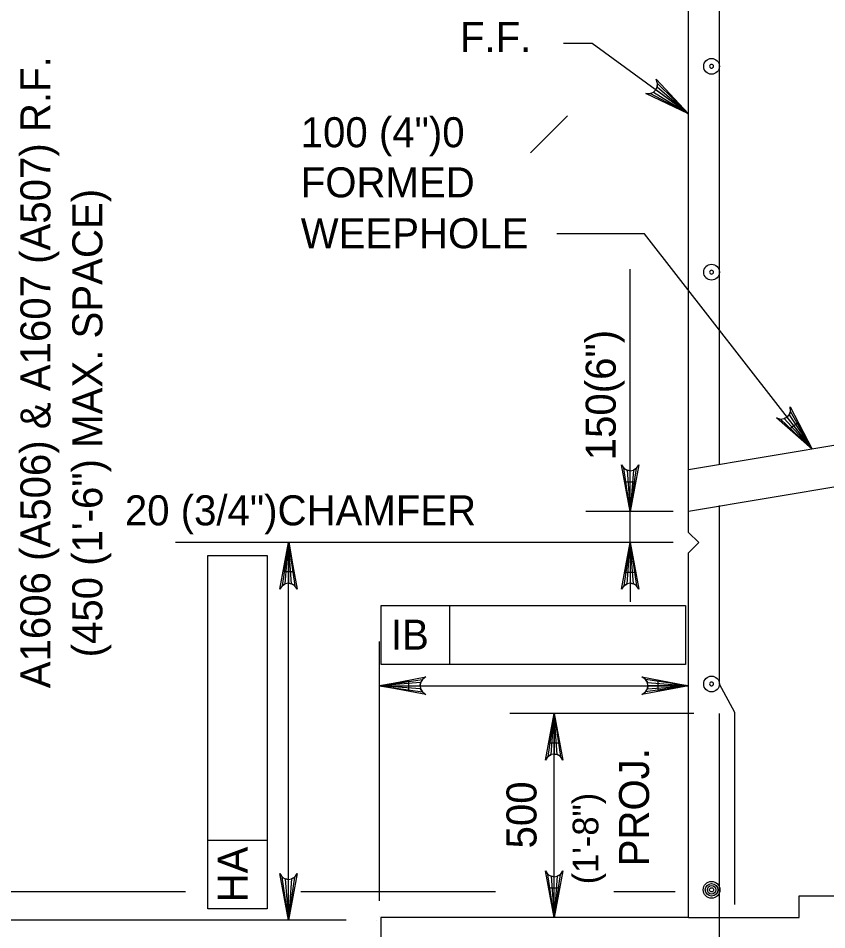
# Model space of a CAD drawing. Extents: x 634540 to 640306, y 296059 to 300275.
# Drawn here: x 639037.4 to 639118.2, y 298220.1 to 298311.1 of the extents above; entities that cross this region are included whole.
import ezdxf

# ---------------------------------------------------------------- set-up
doc = ezdxf.new("R2010")
doc.units = 0
for name, color, linetype in [('3', 7, 'Continuous'), ('4', 7, 'Continuous'), ('5', 7, 'Continuous'), ('6', 7, 'Continuous'), ('7', 7, 'Continuous'), ('9', 7, 'Continuous')]:
    doc.layers.add(name, color=color, linetype=linetype)

# ---------------------------------------------------------------- blocks, each defined once
blk = doc.blocks.new('B')
at = {"layer": '3'}
blk.add_circle((0, 0), 0.16, dxfattribs=at)
for start, end in [(0, 180), (180, 0)]:
    blk.add_arc((0, 0), 0.0391, start, end, dxfattribs=at)

msp = doc.modelspace()

# ---------------------------------------------------------------- linework, layer by layer
at = {"layer": '3'}
for p, q in [((639094.771, 298308.588), (639091.913, 298308.588)), ((639104.407, 298301.563), (639094.771, 298308.588)), ((639088.624, 298297.668), (639092.312, 298301.356)), ((639098.569, 298261.863), (639098.569, 298286.062)), ((639098.569, 298264.815), (639098.569, 298267.769)), ((639102.869, 298261.863), (639094.14, 298261.863)), ((639098.569, 298258.742), (639098.569, 298261.863)), ((639104.407, 298259.769), (639105.432, 298258.742)), ((639102.869, 298258.742), (639053.144, 298258.742)), ((639064.432, 298221.038), (639064.432, 298258.742)), ((639097.848, 298258.742), (639094.14, 298258.742)), ((639098.569, 298258.742), (639098.569, 298252.838)), ((639104.407, 298257.717), (639105.432, 298258.742)), ((639056.388, 298222.165), (639056.388, 298257.467)), ((639056.388, 298257.467), (639062.295, 298257.467)), ((639062.295, 298257.467), (639062.295, 298222.165)), ((639073.706, 298252.469), (639104.084, 298252.469)), ((639073.706, 298246.564), (639073.706, 298252.469)), ((639080.552, 298246.564), (639080.552, 298252.469)), ((639104.084, 298252.469), (639104.084, 298246.564)), ((639104.084, 298246.564), (639073.706, 298246.564)), ((639104.92, 298241.689), (639086.542, 298241.689)), ((639090.971, 298221.311), (639090.971, 298241.689)), ((639062.295, 298229.009), (639056.388, 298229.009)), ((639054.144, 298223.884), (639031.775, 298223.884)), ((639085.12, 298223.885), (639065.662, 298223.885)), ((639103.058, 298223.885), (639096.939, 298223.885)), ((639062.295, 298222.165), (639056.388, 298222.165)), ((639070.189, 298221.038), (639014.561, 298221.038)), ((639044.617, 298221.038), (639032.047, 298221.038))]:
    msp.add_line(p, q, dxfattribs=at)
for points in [[(639104.407, 298301.563), (639100.126, 298303.602), (639100.563, 298303.592), (639100.896, 298303.736), (639101.124, 298303.957), (639101.265, 298304.24), (639101.299, 298304.602), (639101.157, 298305.015), (639104.407, 298301.563), (639101.299, 298304.602), (639101.265, 298304.24), (639104.407, 298301.563), (639101.124, 298303.957), (639100.896, 298303.736), (639104.407, 298301.563), (639100.563, 298303.592)], [(639116.728, 298268.074), (639113.176, 298271.215), (639113.593, 298271.084), (639113.953, 298271.13), (639114.232, 298271.28), (639114.447, 298271.513), (639114.578, 298271.851), (639114.555, 298272.288), (639116.728, 298268.074), (639114.578, 298271.851), (639114.447, 298271.513), (639116.728, 298268.074), (639114.232, 298271.28), (639113.953, 298271.13), (639116.728, 298268.074), (639113.593, 298271.084)], [(639098.569, 298261.863), (639097.696, 298266.524), (639097.944, 298266.165), (639098.257, 298265.98), (639098.569, 298265.926), (639098.882, 298265.98), (639099.194, 298266.165), (639099.442, 298266.524), (639098.569, 298261.863), (639099.194, 298266.165), (639098.882, 298265.98), (639098.569, 298261.863), (639098.569, 298265.926), (639098.257, 298265.98), (639098.569, 298261.863), (639097.944, 298266.165)], [(639064.432, 298258.742), (639065.305, 298254.081), (639065.057, 298254.44), (639064.745, 298254.625), (639064.432, 298254.679), (639064.12, 298254.625), (639063.807, 298254.44), (639063.559, 298254.081), (639064.432, 298258.742), (639063.807, 298254.44), (639064.12, 298254.625), (639064.432, 298258.742), (639064.432, 298254.679), (639064.745, 298254.625), (639064.432, 298258.742), (639065.057, 298254.44)], [(639098.569, 298258.742), (639099.442, 298254.081), (639099.194, 298254.44), (639098.882, 298254.625), (639098.569, 298254.679), (639098.257, 298254.625), (639097.944, 298254.44), (639097.696, 298254.081), (639098.569, 298258.742), (639097.944, 298254.44), (639098.257, 298254.625), (639098.569, 298258.742), (639098.569, 298254.679), (639098.882, 298254.625), (639098.569, 298258.742), (639099.194, 298254.44)], [(639073.51, 298244.454), (639078.17, 298245.327), (639077.812, 298245.079), (639077.627, 298244.766), (639077.572, 298244.454), (639077.627, 298244.141), (639077.812, 298243.829), (639078.17, 298243.581), (639073.51, 298244.454), (639077.812, 298243.829), (639077.627, 298244.141), (639073.51, 298244.454), (639077.572, 298244.454), (639077.627, 298244.766), (639073.51, 298244.454), (639077.812, 298245.079)], [(639104.407, 298244.454), (639099.746, 298243.581), (639100.105, 298243.829), (639100.29, 298244.141), (639100.344, 298244.454), (639100.29, 298244.766), (639100.105, 298245.079), (639099.746, 298245.327), (639104.407, 298244.454), (639100.105, 298245.079), (639100.29, 298244.766), (639104.407, 298244.454), (639100.344, 298244.454), (639100.29, 298244.141), (639104.407, 298244.454), (639100.105, 298243.829)], [(639090.971, 298241.689), (639091.844, 298237.028), (639091.596, 298237.387), (639091.283, 298237.572), (639090.971, 298237.626), (639090.658, 298237.572), (639090.346, 298237.387), (639090.098, 298237.028), (639090.971, 298241.689), (639090.346, 298237.387), (639090.658, 298237.572), (639090.971, 298241.689), (639090.971, 298237.626), (639091.283, 298237.572), (639090.971, 298241.689), (639091.596, 298237.387)], [(639064.432, 298221.038), (639063.559, 298225.699), (639063.807, 298225.34), (639064.12, 298225.155), (639064.432, 298225.101), (639064.745, 298225.155), (639065.057, 298225.34), (639065.305, 298225.699), (639064.432, 298221.038), (639065.057, 298225.34), (639064.745, 298225.155), (639064.432, 298221.038), (639064.432, 298225.101), (639064.12, 298225.155), (639064.432, 298221.038), (639063.807, 298225.34)], [(639090.971, 298221.311), (639090.098, 298225.972), (639090.346, 298225.613), (639090.658, 298225.428), (639090.971, 298225.374), (639091.283, 298225.428), (639091.596, 298225.613), (639091.844, 298225.972), (639090.971, 298221.311), (639091.596, 298225.613), (639091.283, 298225.428), (639090.971, 298221.311), (639090.971, 298225.374), (639090.658, 298225.428), (639090.971, 298221.311), (639090.346, 298225.613)]]:
    msp.add_lwpolyline(points, dxfattribs=at)
for points in [[(639098.078, 298264.815), (639099.061, 298264.815), (639098.569, 298261.863)], [(639064.953, 298255.833), (639063.968, 298255.833), (639064.461, 298258.788)], [(639098.078, 298255.79), (639099.061, 298255.79), (639098.569, 298258.742)], [(639090.477, 298238.737), (639091.463, 298238.737), (639090.971, 298241.689)], [(639090.477, 298224.263), (639091.463, 298224.263), (639090.971, 298221.311)]]:
    msp.add_lwpolyline(points, close=True, dxfattribs=at)
at = {"layer": '4'}
for p, q in [((639099.98, 298289.589), (639091.229, 298289.589)), ((639116.728, 298268.074), (639099.98, 298289.589)), ((639073.51, 298222.978), (639073.51, 298248.883)), ((639073.51, 298244.454), (639104.407, 298244.454))]:
    msp.add_line(p, q, dxfattribs=at)
for points in [[(639115.301, 298270.705), (639114.526, 298270.101), (639116.728, 298268.074)], [(639076.462, 298243.962), (639076.462, 298244.945), (639073.51, 298244.454)], [(639101.359, 298243.962), (639101.359, 298244.945), (639104.313, 298244.454)]]:
    msp.add_lwpolyline(points, close=True, dxfattribs=at)
at = {"layer": '5'}
for p, q in [((639107.472, 298266.599), (639107.472, 298340.564)), ((639107.472, 298244.62), (639107.472, 298262.442)), ((639109.009, 298241.779), (639107.472, 298244.62)), ((639107.472, 298199.32), (639107.472, 298241.689)), ((639109.009, 298222.592), (639109.009, 298241.779))]:
    msp.add_line(p, q, dxfattribs=at)
for radius in [0.833, 0.625, 0.417, 0.208]:
    msp.add_circle((639106.696, 298224.073), radius, dxfattribs=at)
at = {"layer": '6'}
msp.add_lwpolyline([(639104.407, 298221.311), (639115.439, 298221.311), (639115.439, 298223.474), (639122.631, 298223.474), (639122.631, 298221.311), (639134.281, 298221.311)], dxfattribs=at)
at = {"layer": '7'}
for p, q in [((639104.313, 298244.454), (639104.313, 298244.454)), ((639073.253, 298221.038), (639073.253, 298221.038)), ((639073.51, 298221.438), (639073.51, 298221.438)), ((639104.313, 298221.303), (639104.313, 298221.303))]:
    msp.add_line(p, q, dxfattribs=at)
at = {"layer": '9'}
for p, q in [((639104.407, 298259.769), (639104.407, 298357.565)), ((639130.198, 298270.317), (639104.407, 298266.019)), ((639147.524, 298269.049), (639104.407, 298261.863)), ((639104.407, 298221.311), (639104.407, 298257.717)), ((639104.407, 298221.311), (639073.647, 298221.311)), ((639073.647, 298221.311), (639073.647, 298196.704))]:
    msp.add_line(p, q, dxfattribs=at)

# ---------------------------------------------------------------- block references
at = {"layer": '3', "xscale": 4.921475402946, "yscale": 4.921475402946, "rotation": 90}
for p in [(639106.695, 298306.307), (639106.695, 298285.747), (639106.695, 298244.631)]:
    msp.add_blockref('B', p, dxfattribs=at)

# ---------------------------------------------------------------- texts
at = {"layer": '3'}
for s, height, p in [('F.F.', 3.0001, (639081.558, 298307.725)), ('100 (4")0', 3.0001, (639065.659, 298298.221)), ('FORMED', 3.0001, (639065.659, 298293.221)), ('WEEPHOLE', 3.0001, (639065.659, 298288.137)), ('20 (3/4")CHAMFER', 3.00014, (639048.092, 298260.467)), ('IB', 3.0001, (639074.662, 298248.048))]:
    msp.add_text(s, height=height, dxfattribs=at).set_placement(p)
for s, height, p in [('A1606 (A506) & A1607 (A507) R.F.', 3.00014, (639040.658, 298244.2)), ('(450 (1\'-6") MAX. SPACE)', 3.00014, (639045.848, 298247.285)), ('150(6")', 3.0001, (639097.123, 298266.963)), ('PROJ.', 3.0001, (639100.453, 298226.418)), ('500', 3.0001, (639089.208, 298228.205)), ('(1\'-8")', 2.5722, (639095.388, 298224.624)), ('HA', 3.0001, (639060.37, 298222.813))]:
    msp.add_text(s, height=height, rotation=90, dxfattribs=at).set_placement(p)

doc.saveas('drawing.dxf')
